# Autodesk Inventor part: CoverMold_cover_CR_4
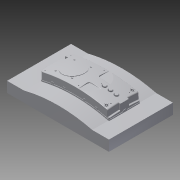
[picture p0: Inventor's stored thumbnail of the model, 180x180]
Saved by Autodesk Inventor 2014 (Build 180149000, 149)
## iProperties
Created: 2009-12
Part Number: CoverMold_cover_CR_4
Document SubType Name: Modeling
Designer: gaom
Density: 1 g/cm^3
Material: Generic
Appearance: Default
Author: gaom
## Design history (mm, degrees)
node "CoverMold_cover_CR_Base"
feature "Solid1::CoverMold_cover_CR_Base"
tag "TaggingFeature1"
body "Solid1"
